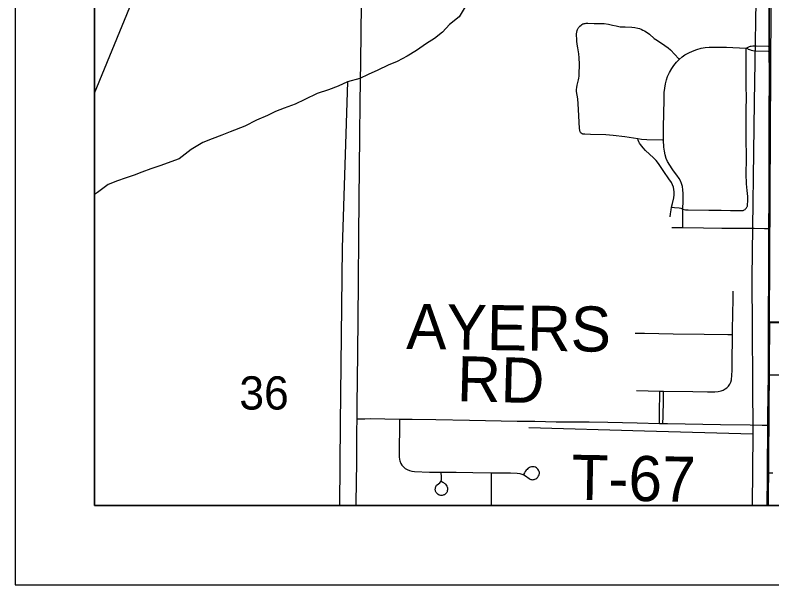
# Model space of a CAD drawing. Extents: x 0 to 40.2, y 0 to 22.
# Drawn here: x 2 to 2.953, y 14 to 14.718 of the extents above; entities that cross this region are included whole.
import ezdxf

# ---------------------------------------------------------------- set-up
doc = ezdxf.new("R2010")
doc.units = 0
for name, color, linetype in [('GM_X_Adjacent_County', 7, 'Continuous'), ('GM_X_City_Street', 7, 'Continuous'), ('GM_X_Corporation', 7, 'Continuous'), ('GM_X_County_Road_Text', 7, 'Continuous'), ('GM_X_Major_Lake_Text', 7, 'Continuous'), ('GM_X_Major_River', 7, 'Continuous'), ('GM_X_Minor_Lake', 7, 'Continuous'), ('GM_X_Rail_Line', 7, 'Continuous'), ('GM_X_Township_Road', 7, 'Continuous')]:
    doc.layers.add(name, color=color, linetype=linetype)

msp = doc.modelspace()

# ---------------------------------------------------------------- linework, layer by layer
at = {"layer": 'GM_X_Adjacent_County'}
for p, q in [((2, 21), (2, 14)), ((2.1, 20.9), (2.1, 14.1)), ((2.1, 14.1), (8.9, 14.1)), ((2.1, 14.1), (2.1, 14.1)), ((2, 14), (9, 14))]:
    msp.add_line(p, q, dxfattribs=at)
at = {"layer": 'GM_X_Corporation'}
for points in [[(2.1, 17.42646), (2.1, 14.1), (8.77357, 14.1)], [(2.1, 17.42646), (2.1, 14.1), (2.94693, 14.1), (2.94741, 14.13708), (2.94744, 14.1416), (2.94781, 14.20185), (2.94787, 14.21147), (2.94843, 14.26536), (2.94844, 14.26618), (2.94856, 14.31965), (2.94861, 14.33092), (2.94864, 14.33893), (2.94892, 14.38928), (2.94902, 14.42908), (2.94908, 14.44943), (2.9492, 14.48691), (2.9495, 14.58951), (2.94958, 14.64299), (2.94954, 14.67294), (2.94953, 14.67911), (2.9495, 14.70455), (2.94935, 14.73937)], [(2.94935, 14.73937), (2.9495, 14.70455), (2.94953, 14.67911), (2.94954, 14.67294), (2.94958, 14.64299), (2.9495, 14.58951), (2.9492, 14.48691), (2.94908, 14.44943), (2.94902, 14.42908), (2.94892, 14.38928), (2.94864, 14.33893), (2.94861, 14.33092), (2.94856, 14.31965), (2.94844, 14.26618), (2.94843, 14.26536), (2.94787, 14.21147), (2.94781, 14.20185), (2.94744, 14.1416), (2.94741, 14.13708), (2.94693, 14.1), (8.77357, 14.1)]]:
    msp.add_lwpolyline(points, dxfattribs=at)
for points in [[(2.9569, 15.35216), (3.74809, 15.33567), (3.751, 14.32404), (2.94986, 14.33119), (2.95186, 14.72799)], [(2.1, 14.73705), (2.1, 14.1), (2.94793, 14.1), (2.94986, 14.33119), (2.95186, 14.72799)], [(2.94793, 14.1), (3.75451, 14.1), (3.751, 14.32404), (2.94986, 14.33119)]]:
    msp.add_lwpolyline(points, close=True, dxfattribs=at)
at = {"layer": 'GM_X_Major_Lake_Text'}
msp.add_line((2.94766, 14.14104), (2.94804, 14.2013), dxfattribs=at)
for points in [[(2.94977, 14.67239), (2.94976, 14.67855), (2.94973, 14.704), (2.94957, 14.73881), (2.94903, 14.78546), (2.94915, 14.82712), (2.94895, 14.85946), (2.94916, 14.8893), (2.94922, 14.92538), (2.94924, 14.949), (2.94932, 14.98765), (2.94937, 15.01752)], [(2.43048, 14.20928), (2.43067, 14.2263), (2.43136, 14.29159), (2.43214, 14.38112), (2.43279, 14.43957), (2.43313, 14.4856), (2.43394, 14.56517), (2.43433, 14.60807), (2.43518, 14.65936), (2.43592, 14.73133), (2.43578, 14.76552), (2.43549, 14.84213), (2.43572, 14.90729), (2.43598, 14.98135)], [(2.94931, 14.44887), (2.94942, 14.48636), (2.94973, 14.58896), (2.94981, 14.64244), (2.94977, 14.67239)], [(2.94883, 14.33036), (2.94886, 14.33838), (2.94915, 14.38873), (2.94925, 14.42852), (2.94931, 14.44887)], [(2.94866, 14.2648), (2.94867, 14.26562), (2.94879, 14.3191), (2.94883, 14.33036)], [(2.94804, 14.2013), (2.94809, 14.21091), (2.94866, 14.2648)], [(2.42938, 14.1), (2.4294, 14.10325), (2.43003, 14.15479), (2.43031, 14.19337), (2.43048, 14.20928)], [(2.94717, 14.1), (2.94763, 14.13653), (2.94766, 14.14104)]]:
    msp.add_lwpolyline(points, dxfattribs=at)
at = {"layer": 'GM_X_Major_River'}
msp.add_lwpolyline([(2.1, 14.61932), (2.26141, 15.01317), (2.2895, 15.07553), (2.32112, 15.14229), (2.3457, 15.18621), (2.37995, 15.2231), (2.43965, 15.26499), (2.73307, 15.44158)], dxfattribs=at)
at = {"layer": 'GM_X_Minor_Lake'}
for points in [[(2.93846, 15.04034), (2.93695, 14.92461), (2.93326, 14.7865), (2.93057, 14.60815), (2.9277, 14.38728), (2.92893, 14.18988), (2.92792, 14.1)], [(2.56645, 14.7281), (2.55911, 14.71567), (2.54689, 14.70595), (2.53808, 14.69619), (2.52815, 14.68835), (2.51787, 14.68202), (2.50529, 14.67307), (2.49349, 14.66601), (2.48093, 14.65933), (2.46954, 14.65454), (2.45661, 14.64825), (2.44446, 14.64309), (2.43419, 14.6379), (2.41827, 14.63355), (2.40687, 14.62838), (2.39472, 14.6236), (2.3803, 14.61884), (2.36472, 14.61145), (2.35255, 14.60553), (2.33888, 14.60038), (2.32788, 14.59635), (2.31761, 14.59116), (2.30393, 14.58526), (2.2891, 14.57785), (2.27088, 14.57087), (2.26024, 14.56645), (2.2481, 14.56205), (2.23633, 14.55726), (2.22148, 14.54834), (2.2066, 14.53676), (2.1823, 14.52795), (2.17092, 14.52392), (2.15953, 14.51989), (2.14966, 14.51621), (2.13866, 14.51218), (2.12879, 14.50888), (2.11702, 14.50448), (2.10367, 14.4944), (2.1, 14.49167)], [(2.41827, 14.63355), (2.41178, 14.42449), (2.40929, 14.20323), (2.40841, 14.1)], [(2.92893, 14.18988), (2.79222, 14.19349), (2.64684, 14.19797)]]:
    msp.add_lwpolyline(points, dxfattribs=at)
at = {"layer": 'GM_X_Rail_Line'}
for p, q in [((2.82686, 14.45035), (2.84056, 14.45011)), ((2.78219, 14.24467), (2.81179, 14.24413))]:
    msp.add_line(p, q, dxfattribs=at)
for points in [[(2.71283, 14.56896), (2.712, 14.56987), (2.71134, 14.57091), (2.71079, 14.57266), (2.71046, 14.57509), (2.70931, 14.59867), (2.70885, 14.60613), (2.70826, 14.61229), (2.70692, 14.62149), (2.70679, 14.62396), (2.70701, 14.62641), (2.70752, 14.62945), (2.70932, 14.63604), (2.70975, 14.63848), (2.70998, 14.64095), (2.70998, 14.64281), (2.71038, 14.65582), (2.71023, 14.66389), (2.7098, 14.66883), (2.7086, 14.67648), (2.70772, 14.68099), (2.70724, 14.68493), (2.70703, 14.68768), (2.70683, 14.69201), (2.70693, 14.69407), (2.70724, 14.69634), (2.70771, 14.69818), (2.70822, 14.69955), (2.70893, 14.70121), (2.70954, 14.70227), (2.71029, 14.70321), (2.71102, 14.70394), (2.71261, 14.70531)], [(2.71261, 14.70531), (2.71359, 14.70601), (2.71469, 14.7066), (2.71573, 14.70699), (2.71659, 14.7072), (2.71751, 14.70739), (2.71905, 14.70751), (2.72108, 14.7075), (2.72915, 14.7074), (2.74142, 14.70701), (2.7471, 14.7063), (2.75196, 14.7053), (2.75685, 14.70426), (2.76005, 14.70356), (2.76186, 14.70319), (2.76352, 14.70297), (2.76547, 14.70282), (2.76788, 14.70289), (2.77657, 14.70269), (2.78028, 14.7023), (2.78391, 14.70151), (2.78611, 14.70083), (2.78802, 14.70006), (2.79035, 14.69901), (2.79251, 14.69794), (2.79571, 14.69604), (2.79866, 14.69378), (2.80467, 14.68838), (2.80666, 14.68689), (2.80883, 14.68567), (2.81819, 14.67956), (2.82218, 14.67663), (2.82497, 14.67416), (2.83054, 14.66831), (2.83507, 14.66329), (2.83621, 14.66203)], [(2.83621, 14.66203), (2.83971, 14.66503), (2.84335, 14.66757), (2.84828, 14.67039), (2.85286, 14.67253), (2.85822, 14.67444), (2.86369, 14.67592), (2.86867, 14.67683), (2.8737, 14.6773), (2.88121, 14.67742), (2.89556, 14.67727), (2.90381, 14.67705), (2.92057, 14.67631)], [(2.92036, 14.47438), (2.9208, 14.47499), (2.92142, 14.47603), (2.9217, 14.47659), (2.92189, 14.47721), (2.92208, 14.47825), (2.92225, 14.47973), (2.92247, 14.48295), (2.9223, 14.48925), (2.9215, 14.4967), (2.92082, 14.50533), (2.92032, 14.51773), (2.92029, 14.52574), (2.9206, 14.52815), (2.92062, 14.5388), (2.92052, 14.56244), (2.92034, 14.57797), (2.92057, 14.59039), (2.92046, 14.59974), (2.92062, 14.61277), (2.92043, 14.62958), (2.9202, 14.64883), (2.92044, 14.66371), (2.92057, 14.67631)], [(2.92057, 14.67631), (2.92203, 14.67704), (2.92298, 14.67751), (2.92384, 14.67794), (2.92457, 14.67831), (2.92579, 14.6786), (2.92684, 14.67885), (2.92891, 14.67901), (2.93105, 14.67917), (2.93311, 14.67925), (2.94812, 14.67862), (2.94976, 14.67855)], [(2.92057, 14.67631), (2.92208, 14.67552), (2.92311, 14.67488), (2.92438, 14.67433), (2.92575, 14.6739), (2.92668, 14.67361), (2.92865, 14.67318), (2.93082, 14.67296), (2.93225, 14.67281), (2.94804, 14.67243), (2.94977, 14.67239)], [(2.81642, 14.56002), (2.81637, 14.57214), (2.81673, 14.59827), (2.81695, 14.60635), (2.81729, 14.62007), (2.81779, 14.62571), (2.81873, 14.63131), (2.81998, 14.63621), (2.82148, 14.64039), (2.8239, 14.64553), (2.82668, 14.65047), (2.82918, 14.65414), (2.83282, 14.6585), (2.83621, 14.66203)], [(2.78387, 14.56171), (2.76772, 14.56449), (2.7529, 14.56611), (2.74361, 14.56684), (2.72436, 14.56753), (2.71741, 14.5676), (2.71617, 14.56764), (2.71485, 14.56782), (2.71389, 14.56822), (2.71283, 14.56896)], [(2.81642, 14.56002), (2.81523, 14.56006), (2.79537, 14.5608), (2.78856, 14.56114), (2.78387, 14.56171)], [(2.82656, 14.47587), (2.82748, 14.48038), (2.82912, 14.48766), (2.82966, 14.49135), (2.8298, 14.49508), (2.8295, 14.49817), (2.82883, 14.50121), (2.82776, 14.50412), (2.8263, 14.50687), (2.82323, 14.51155), (2.81663, 14.5206), (2.80987, 14.53104), (2.80717, 14.53444), (2.80379, 14.53807), (2.79873, 14.54268), (2.79365, 14.54728), (2.79071, 14.55048), (2.78739, 14.5546), (2.78625, 14.55635), (2.78534, 14.55806), (2.78447, 14.56005), (2.78387, 14.56171)], [(2.8406, 14.47317), (2.84107, 14.48371), (2.84114, 14.49299), (2.84078, 14.49786), (2.84004, 14.50205), (2.83903, 14.50554), (2.83763, 14.50888), (2.83587, 14.51206), (2.83308, 14.51606), (2.82903, 14.52154), (2.82703, 14.52428), (2.82422, 14.52862), (2.82155, 14.53323), (2.81982, 14.53732), (2.81849, 14.54156), (2.81745, 14.54652), (2.81683, 14.55153), (2.81642, 14.56002)], [(2.8248, 14.46384), (2.82505, 14.46756), (2.82586, 14.47246), (2.82656, 14.47587)], [(2.82656, 14.47587), (2.83008, 14.47552), (2.836, 14.47492), (2.8381, 14.47438), (2.8406, 14.47317)], [(2.84056, 14.45011), (2.84057, 14.45941), (2.84058, 14.46941), (2.8406, 14.47317)], [(2.8406, 14.47317), (2.84396, 14.47263), (2.84734, 14.47231), (2.87343, 14.47216), (2.88898, 14.47187), (2.90077, 14.47163), (2.91502, 14.47159), (2.91599, 14.47162), (2.91669, 14.47172), (2.9173, 14.47196), (2.91806, 14.47234), (2.91911, 14.47308), (2.91963, 14.4736), (2.92036, 14.47438)], [(2.84056, 14.45011), (2.86679, 14.44963), (2.88986, 14.44954), (2.93037, 14.4492), (2.94343, 14.44897), (2.94931, 14.44887)], [(2.90314, 14.31555), (2.90321, 14.32189), (2.90386, 14.36049), (2.9042, 14.36982)], [(2.94866, 14.2648), (2.94867, 14.26562), (2.94879, 14.3191), (2.94883, 14.33036)], [(2.94883, 14.33036), (2.95657, 14.33034), (2.98828, 14.33024), (3.04425, 14.33021), (3.09215, 14.33023), (3.13568, 14.33005), (3.16117, 14.33004), (3.21816, 14.33004)], [(2.78049, 14.31693), (2.7923, 14.31691), (2.82835, 14.31622), (2.86752, 14.31566), (2.89736, 14.31557), (2.90314, 14.31555)], [(2.90286, 14.27021), (2.90276, 14.27892), (2.90314, 14.31555)], [(2.81179, 14.24413), (2.81651, 14.24404), (2.85324, 14.24355), (2.87185, 14.24334), (2.88111, 14.24326), (2.88534, 14.2436), (2.88884, 14.24438), (2.8916, 14.24547), (2.89415, 14.24694), (2.896, 14.24838), (2.89806, 14.2505), (2.89974, 14.25291), (2.90103, 14.25557), (2.90188, 14.25841), (2.90254, 14.26415), (2.90286, 14.27021)], [(2.94804, 14.2013), (2.94809, 14.21091), (2.94866, 14.2648)], [(2.94866, 14.2648), (2.95697, 14.2648), (2.96946, 14.2648), (2.99197, 14.26481)], [(2.81121, 14.20344), (2.81127, 14.21199), (2.81135, 14.22307), (2.81163, 14.23662), (2.81179, 14.24413)], [(2.81555, 14.20333), (2.81573, 14.21213), (2.81615, 14.23266), (2.81651, 14.24404)], [(2.43048, 14.20928), (2.44034, 14.20936), (2.44717, 14.20942), (2.48384, 14.20893)], [(2.48384, 14.20893), (2.48377, 14.20239), (2.48339, 14.16755), (2.48344, 14.1614), (2.48389, 14.15786), (2.48433, 14.15617), (2.48569, 14.15285), (2.48692, 14.15086), (2.48886, 14.14864), (2.49114, 14.14673), (2.49367, 14.14519), (2.49641, 14.14406), (2.4993, 14.14332), (2.50289, 14.14289), (2.5215, 14.14219), (2.53638, 14.14211)], [(2.48384, 14.20893), (2.50002, 14.20872), (2.52987, 14.20815), (2.57216, 14.20738), (2.63188, 14.20617), (2.65427, 14.20619), (2.681, 14.2056), (2.72268, 14.20538), (2.7463, 14.20484), (2.783, 14.20409), (2.81121, 14.20344)], [(2.81121, 14.20344), (2.81555, 14.20333), (2.82155, 14.2032), (2.88811, 14.20204), (2.92544, 14.20148), (2.94034, 14.20136), (2.94804, 14.2013)], [(2.5997, 14.14128), (2.60546, 14.14122), (2.62352, 14.14102), (2.63227, 14.14077), (2.63546, 14.14035), (2.63799, 14.13965), (2.64038, 14.13857), (2.6426, 14.1372), (2.64701, 14.13383), (2.64851, 14.13303), (2.64937, 14.13277), (2.65019, 14.1326), (2.65102, 14.13252), (2.65221, 14.13257), (2.6534, 14.13277), (2.6543, 14.13302), (2.65555, 14.1337), (2.65691, 14.13462), (2.65811, 14.13582), (2.65907, 14.13721), (2.65975, 14.13875), (2.66014, 14.14038), (2.66016, 14.14142), (2.65979, 14.143), (2.65908, 14.14455), (2.6581, 14.14591), (2.65739, 14.14672), (2.65643, 14.14746), (2.65501, 14.14831), (2.65345, 14.14879), (2.65178, 14.14891), (2.65011, 14.1487), (2.64849, 14.14819), (2.64759, 14.14778), (2.6465, 14.14708), (2.64558, 14.14642), (2.64463, 14.14554), (2.64358, 14.1444), (2.64232, 14.14263), (2.64135, 14.14094), (2.64025, 14.139)], [(2.53645, 14.1305), (2.53844, 14.12935), (2.53937, 14.12881), (2.54028, 14.12819), (2.54106, 14.12753), (2.54197, 14.12667), (2.54287, 14.12552), (2.54345, 14.1245), (2.54382, 14.12351), (2.54415, 14.12244), (2.54437, 14.12103), (2.54431, 14.11964), (2.54411, 14.11836), (2.54374, 14.11737), (2.54333, 14.11655), (2.54275, 14.11569), (2.54197, 14.1147), (2.54144, 14.11425), (2.5405, 14.11363), (2.53971, 14.1133), (2.5387, 14.11303), (2.53749, 14.11277), (2.53597, 14.11268), (2.53465, 14.11289), (2.53381, 14.11319), (2.5327, 14.11371), (2.53176, 14.1145), (2.53095, 14.1154), (2.5302, 14.11644), (2.52976, 14.11716), (2.52936, 14.11808), (2.52914, 14.11906), (2.52903, 14.11991), (2.5291, 14.12176), (2.52926, 14.12264), (2.52954, 14.12357), (2.53009, 14.12467), (2.53066, 14.12543), (2.5313, 14.12606), (2.53478, 14.12869), (2.536, 14.13006), (2.53652, 14.13117), (2.53674, 14.13238), (2.53663, 14.13548), (2.53638, 14.14211)], [(2.53638, 14.14211), (2.53952, 14.14209), (2.55508, 14.14192), (2.57623, 14.14153), (2.5997, 14.14128)], [(2.59956, 14.1), (2.59968, 14.13456), (2.5997, 14.14128)], [(2.94766, 14.14104), (2.95411, 14.14096)]]:
    msp.add_lwpolyline(points, dxfattribs=at)
at = {"layer": 'GM_X_Township_Road'}
msp.add_lwpolyline([(2.1, 20.9), (8.9, 20.9), (8.9, 14.1), (2.1, 14.1)], close=True, dxfattribs=at)

# ---------------------------------------------------------------- texts
at = {"layer": 'GM_X_City_Street'}
msp.add_text('36', height=0.041856, rotation=0.00001, dxfattribs=at).set_placement((2.28227, 14.22087))
at = {"layer": 'GM_X_County_Road_Text'}
for s, rotation, p in [('AYERS', 359.16627, (2.49229, 14.29733)), ('RD', 358.51351, (2.55592, 14.23151)), ('T-67', 358.97025, (2.70009, 14.10722))]:
    msp.add_text(s, height=0.056818, rotation=rotation, dxfattribs=at).set_placement(p)

doc.saveas('drawing.dxf')
